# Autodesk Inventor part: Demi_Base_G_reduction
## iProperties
Shininess: 64.0
Length Units: 11269
Angle Units: 11279
Time Units: 11290
Mass Units: 11283
Length Display Precision: 3
Angle Display Precision: 2
Compacted: True
Part Number: Demi_Base_G_reduction
Document SubType Name: Modeling
Created: 2008-02
Material: Acier doux
Designer: Pascal
Density: 0.0
Volumn: 0.0
Area: 0.0
PropertySet Name: Model Information
Control State: 0
Master: False
Checked Out: False
MATIERE_PIECE: X2CrNi 18-11
OBSERVATIONS: Tôle ep. 15/10
DESIGNATION: Demi-réduction gauche
Author: Pascal
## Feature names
1. Lissage1
2. Coque1
3. Extrusion1
